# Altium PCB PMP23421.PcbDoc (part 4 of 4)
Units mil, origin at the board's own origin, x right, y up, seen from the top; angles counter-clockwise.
Board outline 2755.91 x 7559.06 mil, 8 copper layers (Top Layer, Signal Layer 1, Signal Layer 2, Signal Layer 3, Signal Layer 4, Signal Layer 5, Signal Layer 6, Bottom Layer), stack 60.4 mil thick; 211 components, 135 nets, 708 pads, 652 vias.
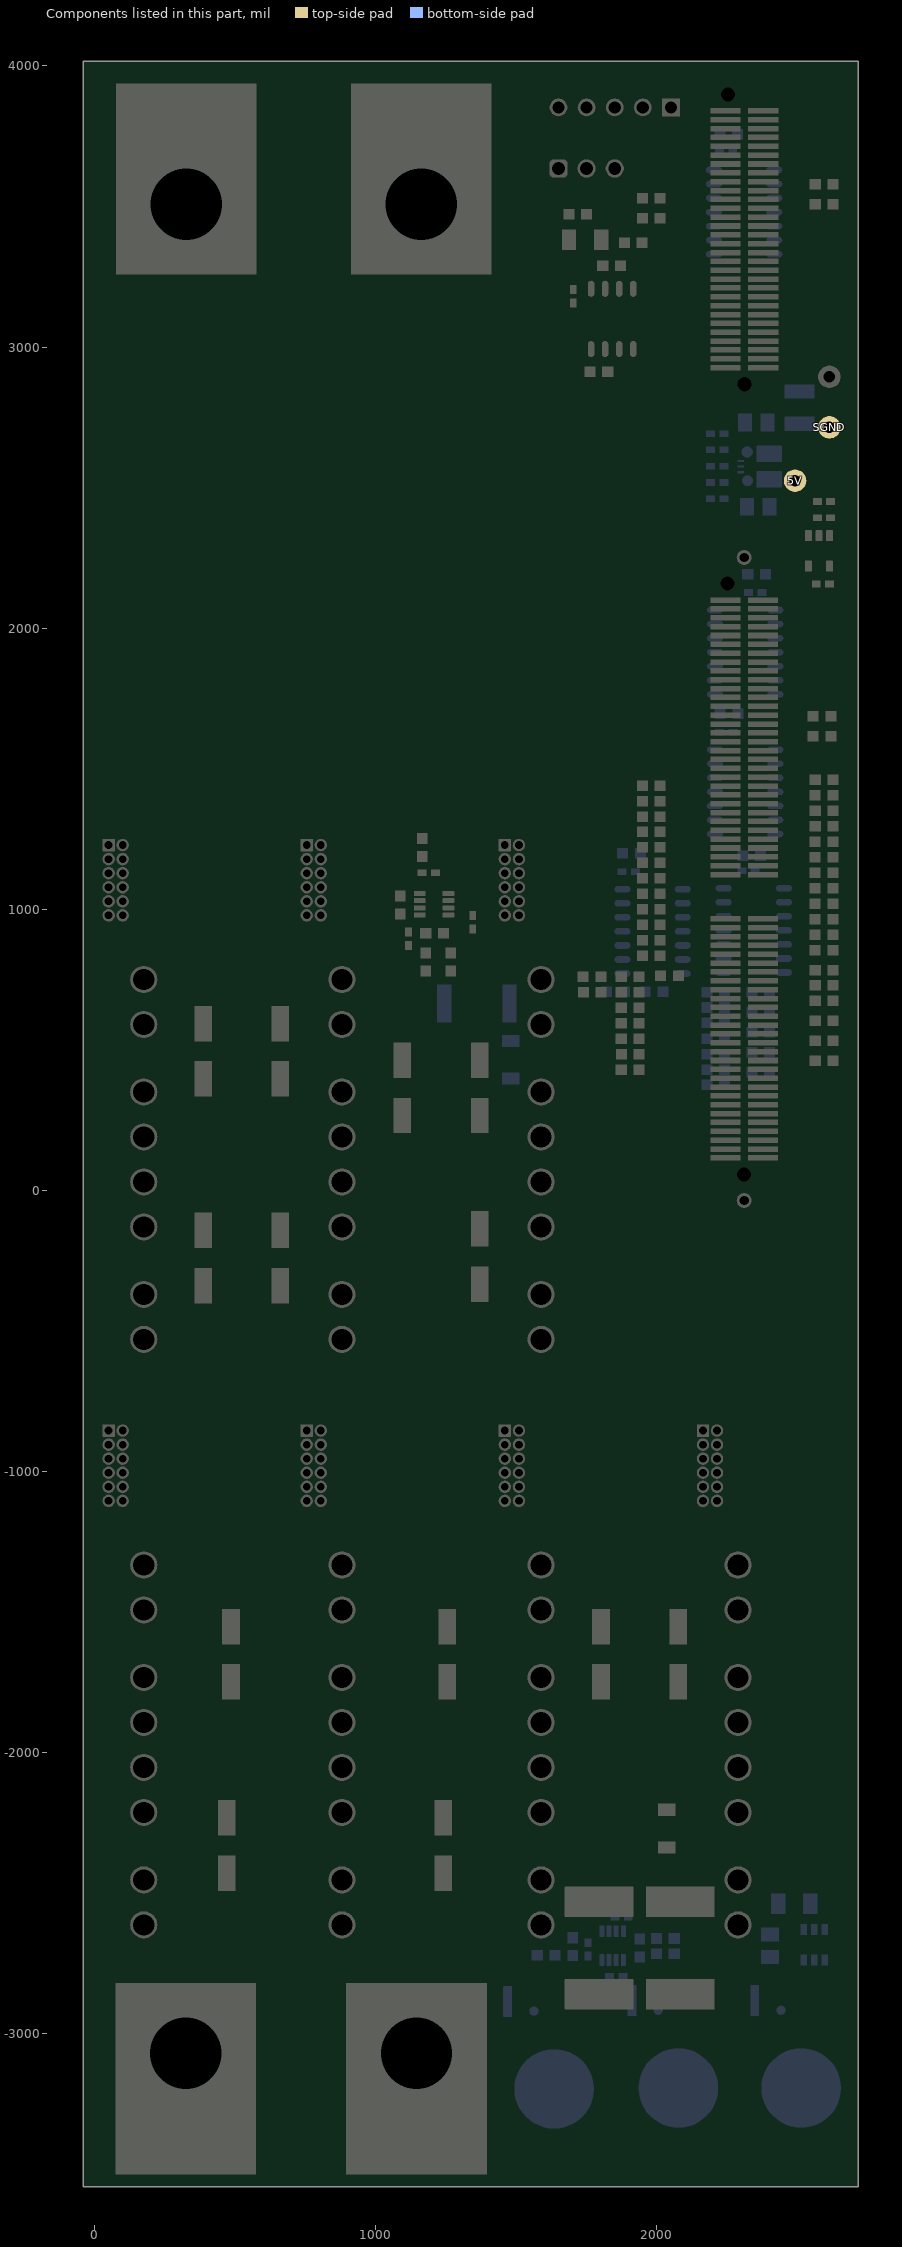
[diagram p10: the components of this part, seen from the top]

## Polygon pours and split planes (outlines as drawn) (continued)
VBAT- on Signal Layer 1 "VBAT-" (solid, remove dead copper, pour order 167): -20,-1960 2390,-1960 2390,-1183.1 2356.91,-1150 1765,-1150 1699.53,-1082.22 1699.53,1525.47 1580,1645 1580,3950 1535,3995 650,3995 605,3950 605,3255 580,3230 10,3230 -20,3200 -20,-1707.96 -18.98,-1708.98 -20,-1710
48VOUT2 on Signal Layer 1 "48Vout2" (solid, remove dead copper, pour order 149): 895.77,-2819.23 850,-2865 850,-3488.58 901.42,-3540 2660,-3540 2715,-3485 2715,-3045 2685,-3015 1465,-3015 1435,-2985 1435,-2860 1394.23,-2819.23
CS-_total_discharge_current_bus on Signal Layer 1 "CS-_total_discharge_current_bus" (solid, remove dead copper, pour order 218): 1900,-2750 1910,-2760 1910,-2785 1920,-2795 1960,-2795 1970,-2785 1970,-2760 1980,-2750 2065,-2750 2065,-2940 1520,-2940 1487.2,-2907.2 1487.2,-2782.8 1520,-2750
CS-_total_discharge_current_bus on Signal Layer 1 "CS-_total_discharge_current_bus" (solid, remove dead copper, pour order 306): 2093.91,-2750 2650.64,-2750 2700,-2799.36 2700,-2910 2670,-2940 2093.91,-2940
SGND on Signal Layer 1 "SGND" (solid, remove dead copper, pour order 332): -18.98,-1975 2390,-1975 2390,-2290.17 2340.17,-2340 1920.27,-2340 1511.68,-2748.59 741.41,-2748.59 700,-2790 700,-3490 665,-3525 14.61,-3525 -18.98,-3491.41
no net on Signal Layer 1 "VBAT-" (solid, remove dead copper, pour order 346): -20,-1960 2390,-1960 2390,-1183.1 2356.91,-1150 1765,-1150 1699.53,-1082.22 1699.53,1525.47 1580,1645 1580,3950 1535,3995 650,3995 605,3950 605,3255 580,3230 10,3230 -20,3200 -20,-1707.96 -18.98,-1708.98 -20,-1710
SGND on Signal Layer 2 "SGND" (solid, remove dead copper, pour order 296): 2450,-2325 2450,-2720 2669.61,-2720 2715.4,-2674.21 2715.4,-1125.22 2715,-1124.82 2715,3970 2685,4000 1640,4000 1588.33,3948.33 1588.55,1701.89 1710,1580.43 1710,-994.12 1850.7,-1134.82 2410,-1134.82 2450,-1174.82
VBAT- on Signal Layer 2 "VBAT-" (solid, remove dead copper, pour order 294): 765,2158.96 945,1978.96 945,1410 1030,1325 1490.71,1325 1580.71,1415 1580.71,2135 1580.71,3969.29 1554.64,3995.36 791.5,3995.36 765,3968.86
CS-_total_charge_current_battery on Signal Layer 2 "CS-_total_charge_current_battery" (solid, remove dead copper, pour order 288): -30,2225 -30,555.1 0,525.1 905.34,525.1 936.42,556.17 936.42,1970.91 748.66,2158.66 750,2160 750,4000 30,4000 -30,3940
CS-_total_charge_current_battery on Signal Layer 2 "CS-" (solid, remove dead copper, pour order 286): 20,-1180 -20,-1220 -20,-1575 20,-1615 2338.59,-1615 2378.59,-1575 2378.59,-1223.59 2335,-1180
SGND on Signal Layer 2 "SGND" (solid, remove dead copper, pour order 276): 14.61,-2715 -18.98,-2748.59 -18.98,-3491.41 14.61,-3525 665,-3525 700,-3490 700,-2750 665,-2715
48VOUT1 on Signal Layer 2 "48Vout1" (solid, remove dead copper, pour order 268): 15,-2310 -18.98,-2343.98 -18.98,-2666.02 15,-2700 1890,-2700 2395,-2700 2435,-2660 2435,-2345.79 2399.21,-2310
CS-_total_charge_current_battery on Signal Layer 2 "CS-_total_charge_current_battery" (solid, remove dead copper, pour order 264): 130,525 105,550 105,790 130,815 911.42,815 936.42,790 936.42,556.42 905,525
48VOUT1 on Signal Layer 2 "48Vout1" (solid, remove dead copper, pour order 250): 125,-265 105,-285 105,-575 125,-595 930,-595 950,-575 950,-285 930,-265
5V on Signal Layer 2 "5V" (solid, remove dead copper, pour order 139): 2443.65,2558.35 2462.77,2577.46 2518.93,2577.46 2533.44,2562.95 2533.44,2497.36 2513.72,2477.64 2467.46,2477.64 2453.68,2463.86 2453.68,2391.02 2447.77,2385.12 2374.94,2385.12 2369.03,2391.02 2369.03,2463.86 2369.03,2554.41 2372.97,2558.35
5V on Signal Layer 2 "5V" (solid, remove dead copper, pour order 178): 2372.97,2558.35 2369.03,2554.41 2369.03,2463.86 2369.03,2391.02 2374.94,2385.12 2447.77,2385.12 2453.68,2391.02 2453.68,2546.54 2441.87,2558.35
48VOUT2 on Signal Layer 2 "48Vout2" (solid, remove dead copper, pour order 153): 870,-2755 850,-2775 850,-3488.58 901.42,-3540 2660,-3540 2715,-3485 2715,-3045 2685,-3015 1465,-3015 1435,-2985 1435,-2820 1370,-2755
CS-_total_discharge_current_bus on Signal Layer 2 "CS-_total_discharge_current_bus" (solid, remove dead copper, pour order 220): 1900,-2750 1910,-2760 1910,-2785 1920,-2795 1960,-2795 1970,-2785 1970,-2760 1980,-2750 2650.64,-2750 2700,-2799.36 2700,-2910 2670,-2940 1520,-2940 1487.2,-2907.2 1487.2,-2782.8 1520,-2750
SGND on Signal Layer 2 "SGND" (solid, remove dead copper, pour order 254): 1670,-181.02 1631.02,-220 1630,-220 -5,-220 -18.98,-206.02 -18.98,110 1670,110 1670,-50
VBAT- on Signal Layer 2 "VBAT-" (solid, remove dead copper, pour order 312): -18.98,120 -18.98,496.02 0,515 924.4,515 1040.29,399.11 1645.9,399.11 1670,375.01 1670,120
SGND on Signal Layer 2 "SGND" (solid, remove dead copper, pour order 314): -18.98,-1975 2380,-1975 2380,-2258.59 2343.59,-2295 15,-2295 -18.98,-2261.02
VBAT- on Signal Layer 2 "VBAT-" (solid, remove dead copper, pour order 316): 15,-1630 2333.59,-1630 2380,-1676.41 2380,-1975 -18.98,-1975 -18.98,-1663.98
SGND on Signal Layer 3 "SGND" (solid, remove dead copper, pour order 298): 1710,1231.5 1703.5,1225 1626.94,1225 1556.94,1155 1492.92,1155 1485,1147.08 1485,936.31 1515,906.31 1710,906.31 1710,-994.12 1850.7,-1134.82 2410,-1134.82 2450,-1174.82 2450,-2720 2669.61,-2720 2715.4,-2674.21 2715.4,-1125.22 2715,-1124.82 2715,3970 2685,4000 1639.92,4000 1589.95,3950.03 1590.16,1700.27 1710,1580.43
VBAT- on Signal Layer 3 "VBAT-" (solid, remove dead copper, pour order 292): 765,2158.96 945,1978.96 945,1410 1030,1325 1490.71,1325 1580.71,1415 1580.71,2135 1580.71,3949.29 1534.64,3995.36 810.36,3995.36 765,3950
CS-_total_charge_current_battery on Signal Layer 3 "CS-_total_charge_current_battery" (solid, remove dead copper, pour order 290): -25,2225 -25,555.1 5,525.1 910.34,525.1 941.42,556.17 941.42,1970.91 753.66,2158.66 755,2160 755,4000 35,4000 -25,3940
CS-_total_charge_current_battery on Signal Layer 3 "CS-" (solid, remove dead copper, pour order 284): 20,-1180 -20,-1220 -20,-1575 20,-1615 2338.59,-1615 2378.59,-1575 2378.59,-1223.59 2335,-1180
SGND on Signal Layer 3 "SGND" (solid, remove dead copper, pour order 274): 14.61,-2715 -18.98,-2748.59 -18.98,-3491.41 14.61,-3525 665,-3525 700,-3490 700,-2750 665,-2715
48VOUT1 on Signal Layer 3 "48Vout1" (solid, remove dead copper, pour order 266): 15,-2310 -18.98,-2343.98 -18.98,-2666.02 15,-2700 1890,-2700 2395,-2700 2435,-2660 2435,-2345.79 2399.21,-2310
CS-_total_charge_current_battery on Signal Layer 3 "CS-_total_charge_current_battery" (solid, remove dead copper, pour order 262): 130,525 105,550 105,790 130,815 911.42,815 936.42,790 936.42,556.42 905,525
SGND on Signal Layer 3 "SGND" (solid, remove dead copper, pour order 258): 1670,-181.02 1631.02,-220 1630,-220 20,-220 -18.98,-181.02 -18.98,110 1670,110 1670,-50
48VOUT1 on Signal Layer 3 "48Vout1" (solid, remove dead copper, pour order 252): 125,-265 105,-285 105,-575 125,-595 930,-595 950,-575 950,-285 930,-265
5V on Signal Layer 3 "5V" (solid, remove dead copper, pour order 138): 2443.65,2558.35 2462.77,2577.46 2518.93,2577.46 2533.44,2562.95 2533.44,2497.36 2513.72,2477.64 2467.46,2477.64 2453.68,2463.86 2453.68,2391.02 2447.77,2385.12 2374.94,2385.12 2369.03,2391.02 2369.03,2463.86 2369.03,2554.41 2372.97,2558.35
5V on Signal Layer 3 "5V" (solid, remove dead copper, pour order 177): 2372.97,2558.35 2369.03,2554.41 2369.03,2463.86 2369.03,2391.02 2374.94,2385.12 2447.77,2385.12 2453.68,2391.02 2453.68,2546.54 2441.87,2558.35
48VOUT2 on Signal Layer 3 "48Vout2" (solid, remove dead copper, pour order 152): 895.77,-2819.23 850,-2865 850,-3488.58 901.42,-3540 2660,-3540 2715,-3485 2715,-3045 2685,-3015 1450,-3015 1435,-3000 1435,-2860 1394.23,-2819.23
CS-_total_discharge_current_bus on Signal Layer 3 "CS-_total_discharge_current_bus" (solid, remove dead copper, pour order 216): 1900,-2750 1910,-2760 1910,-2785 1920,-2795 1960,-2795 1970,-2785 1970,-2760 1980,-2750 2650.64,-2750 2700,-2799.36 2700,-2910 2670,-2940 1520,-2940 1487.2,-2907.2 1487.2,-2782.8 1520,-2750
SGND on Signal Layer 3 "SGND" (solid, remove dead copper, pour order 318): -18.98,-1975 2380,-1975 2380,-2258.59 2343.59,-2295 15,-2295 -18.98,-2261.02
VBAT- on Signal Layer 3 "VBAT-" (solid, remove dead copper, pour order 320): 15,-1630 2333.59,-1630 2380,-1676.41 2380,-1975 -18.98,-1975 -18.98,-1663.98
VBAT- on Signal Layer 3 "VBAT-" (solid, remove dead copper, pour order 322): -18.98,120 -18.98,496.02 0,515 924.4,515 1040.29,399.11 1645.9,399.11 1670,375.01 1670,120
VBAT- on Signal Layer 4 "VBAT-" (solid, remove dead copper, pour order 302): 1580.35,3949.65 1534.64,3995.36 810.36,3995.36 765,3950 765,2158.96 945,1978.96 945,1410 1027.2,1327.8 1482.8,1327.8 1580.71,1425.71 1580.71,2135 1580.71,3949.29
CS-_total_charge_current_battery on Signal Layer 4 "CS-_total_charge_current_battery" (solid, remove dead copper, pour order 300): -25,2225 -25,555.1 5,525.1 910.34,525.1 941.42,556.17 941.42,1970.91 753.66,2158.66 755,2160 755,4000 35,4000 -25,3940
SGND on Signal Layer 4 "SGND" (solid, remove dead copper, pour order 270): 15,-2715 -18.59,-2748.59 -18.59,-3491.41 15,-3525 665.39,-3525 700.39,-3490 700.39,-2750 665.39,-2715
CS-_total_charge_current_battery on Signal Layer 4 "CS-_total_charge_current_battery" (solid, remove dead copper, pour order 260): 130,525 105,550 105,790 130,815 911.42,815 936.42,790 936.42,556.42 905,525
5V on Signal Layer 4 "5V" (solid, remove dead copper, pour order 140): 2443.65,2558.35 2462.77,2577.46 2518.93,2577.46 2533.44,2562.95 2533.44,2497.36 2513.72,2477.64 2467.46,2477.64 2453.68,2463.86 2453.68,2391.02 2447.77,2385.12 2374.94,2385.12 2369.03,2391.02 2369.03,2463.86 2369.03,2554.41 2372.97,2558.35
48VOUT1 on Signal Layer 4 "48VOUT1" (solid, remove dead copper, pour order 185): 2426.12,-2700 2436.12,-2690 2647.96,-2690 2670,-2667.96 2670,-1235 2595,-1160 2126.54,-1160 1885,-918.46 1885,-715 1760,-590 1555,-590 1525.61,-560.61 1525.61,-311.1 1479.51,-265 15,-265 -20,-300 -20,-2675 5,-2700 465,-2700 1820,-2700 1973.26,-2700
48VOUT2 on Signal Layer 4 "48Vout2" (solid, remove dead copper, pour order 150): 880.77,-2819.23 850,-2850 850,-3488.58 901.42,-3540 2660,-3540 2715,-3485 2715,-3045 2685,-3015 1465,-3015 1435,-2985 1435,-2855 1399.23,-2819.23
CS-_total_discharge_current_bus on Signal Layer 4 "CS-_total_discharge_current_bus" (solid, remove dead copper, pour order 214): 1900,-2750 1910,-2760 1910,-2785 1920,-2795 1960,-2795 1970,-2785 1970,-2760 1980,-2750 2650.64,-2750 2700,-2799.36 2700,-2910 2670,-2940 1520,-2940 1487.2,-2907.2 1487.2,-2782.8 1520,-2750
SGND on Signal Layer 4 "SGND" (solid, remove dead copper, pour order 240): 1610,3955 1588.45,3933.45 1588.45,1413.45 1495,1320 0,1320 -20,1300 -20,885 5,860 1665,860 1710,815 1710,-525 1893.72,-708.72 1893.72,-917.23 2129.37,-1152.88 2662.12,-1152.88 2705,-1110 2705,3875 2625,3955
SGND on Signal Layer 4 "SGND" (solid, remove dead copper, pour order 326): 1670,-181.02 1631.02,-220 1630,-220 -5,-220 -18.98,-206.02 -18.98,110 1670,110 1670,-50
VBAT- on Signal Layer 4 "VBAT-" (solid, remove dead copper, pour order 328): -18.98,120 -18.98,496.02 0,515 924.4,515 1040.29,399.11 1645.9,399.11 1670,375.01 1670,120
SGND on Signal Layer 5 "SGND" (solid, remove dead copper, pour order 334): 1699.53,90 1700.27,89.26 1700.27,-190.27 2124.3,-614.3 2124.3,-1814.3 2260.99,-1950.99 2345.99,-1950.99 2390,-1995 2390,-2290.17 2340.17,-2340 1920.27,-2340 1511.68,-2748.59 891.41,-2748.59 820,-2820 820,-3495 790,-3525 14.61,-3525 -18.98,-3491.41 -18.98,90
SGND on Signal Layer 5 "SGND" (solid, remove dead copper, pour order 336): 1710,-185 1765,-240 2132.95,-607.95 2132.95,-1097.78 2175,-1139.82 2365,-1139.82 2405,-1179.82 2405,-2290 2345,-2350 1925,-2350 1825,-2450 1825,-2684.61 1870.39,-2730 2660,-2730 2700,-2690 2700,3935 2640,3995 1635,3995 1590,3950 1590,3938.81 1590.22,1650.22 1710,1530.43
48VOUT2 on Signal Layer 5 "48Vout2" (solid, remove dead copper, pour order 338): 895.77,-2819.23 850,-2865 850,-3488.58 901.42,-3540 2660,-3540 2715,-3485 2715,-3045 2685,-3015 1465,-3015 1435,-2985 1435,-2860 1394.23,-2819.23
CS-_total_discharge_current_bus on Signal Layer 5 "CS-_total_discharge_current_bus" (solid, remove dead copper, pour order 340): 1900,-2750 1910,-2760 1910,-2785 1920,-2795 1960,-2795 1970,-2785 1970,-2760 1980,-2750 2650.64,-2750 2700,-2799.36 2700,-2910 2670,-2940 1520,-2940 1487.2,-2907.2 1487.2,-2782.8 1520,-2750
CS-_total_charge_current_battery on Signal Layer 5 "CS-_total_charge_current_battery" (solid, remove dead copper, pour order 342): 750,3950 700,4000 30,4000 -30,3940 -30,2225 -30,555.1 0,525.1 905.34,525.1 936.42,556.17 936.42,1970.91 748.66,2158.66 750,2160
VBAT- on Signal Layer 5 "VBAT-" (solid, remove dead copper, pour order 344): 945,1410 945,550.91 909.09,515 0,515 -25,490 -25,100 1700.27,100 1700.27,1524.71 1580.71,1645 1580.71,2135 1580.71,3969.29 1554.64,3995.36 791.5,3995.36 765,3968.86 765,2158.96 945,1978.96
SGND on Signal Layer 6 "SGND" (solid, remove dead copper, pour order 348): 1699.53,90 1700.27,89.26 1700.27,-190.27 2124.3,-614.3 2124.3,-1814.3 2260.99,-1950.99 2345.99,-1950.99 2390,-1995 2390,-2290.17 2340.17,-2340 1920.27,-2340 1511.68,-2748.59 891.41,-2748.59 820,-2820 820,-3495 790,-3525 14.61,-3525 -18.98,-3491.41 -18.98,90
48VOUT2 on Signal Layer 6 "48Vout2" (solid, remove dead copper, pour order 350): 895.77,-2819.23 850,-2865 850,-3488.58 901.42,-3540 2660,-3540 2715,-3485 2715,-3045 2685,-3015 1465,-3015 1435,-2985 1435,-2860 1394.23,-2819.23
CS-_total_discharge_current_bus on Signal Layer 6 "CS-_total_discharge_current_bus" (solid, remove dead copper, pour order 352): 1900,-2750 1910,-2760 1910,-2785 1920,-2795 1960,-2795 1970,-2785 1970,-2760 1980,-2750 2650.64,-2750 2700,-2799.36 2700,-2910 2670,-2940 1520,-2940 1487.2,-2907.2 1487.2,-2782.8 1520,-2750
SGND on Signal Layer 6 "SGND" (solid, remove dead copper, pour order 354): 1710,-185 1765,-240 2132.95,-607.95 2132.95,-1097.78 2175,-1139.82 2365,-1139.82 2405,-1179.82 2405,-2290 2345,-2350 1925,-2350 1825,-2450 1825,-2684.61 1870.39,-2730 2660,-2730 2700,-2690 2700,3935 2640,3995 1635,3995 1590,3950 1590,3938.81 1590.22,1650.22 1710,1530.43
VBAT- on Signal Layer 6 "VBAT-" (solid, remove dead copper, pour order 356): 945,1410 945,550.91 909.09,515 0,515 -25,490 -25,100 1700.27,100 1700.27,1524.71 1580.71,1645 1580.71,2135 1580.71,3969.29 1554.64,3995.36 791.5,3995.36 765,3968.86 765,2158.96 945,1978.96
CS-_total_charge_current_battery on Signal Layer 6 "CS-_total_charge_current_battery" (solid, remove dead copper, pour order 358): 750,3951.15 700,4001.15 30,4001.15 -30,3941.15 -30,2226.15 -30,556.25 0,526.25 905.34,526.25 936.42,557.32 936.42,1972.07 748.66,2159.82 750,2161.15

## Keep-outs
Keep-Out Layer:
  text ".Layer_Name" at 60.15,-4415.31 h60

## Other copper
Top Layer:
  text ".Layer_Name" at 60.15,-4415.31 h60
Signal Layer 2:
  pour cut-out: 2245,-2593.24 2245,-2620 2275,-2620 2275,-2593.24
Signal Layer 1:
  pour cut-out: 760.72,-925.18 760.72,-1134.82 837.05,-1134.82 837.05,-925.18
  pour cut-out: 758.67,1160.37 758.67,950.73 835,950.73 835,1160.37
  pour cut-out: 53.67,1156.03 53.67,946.38 130,946.38 130,1156.03
  pour cut-out: 1463.67,1153.97 1463.67,944.32 1540,944.32 1540,1153.97
  pour cut-out: 1469.89,-930.18 1469.89,-1139.82 1546.22,-1139.82 1546.22,-930.18
  pour cut-out: 54.89,-928.7 54.89,-1138.35 131.22,-1138.35 131.22,-928.7
Signal Layer 4:
  pour cut-out: 2245,-2593.24 2245,-2620 2275,-2620 2275,-2593.24
Signal Layer 5:
  pour cut-out: 54.89,-930.18 54.89,-1139.82 131.22,-1139.82 131.22,-930.18
  pour cut-out: 760,-930.18 760,-1139.82 836.33,-1139.82 836.33,-930.18
  pour cut-out: 1464.89,-931.65 1464.89,-1141.3 1541.22,-1141.3 1541.22,-931.65
Signal Layer 6:
  pour cut-out: 54.89,-930.18 54.89,-1139.82 131.22,-1139.82 131.22,-930.18
  pour cut-out: 760,-930.18 760,-1139.82 836.33,-1139.82 836.33,-930.18
  pour cut-out: 1464.89,-931.65 1464.89,-1141.3 1541.22,-1141.3 1541.22,-931.65
Bottom Layer:
  text ".Layer_Name" at 60.15,-4415.31 h60

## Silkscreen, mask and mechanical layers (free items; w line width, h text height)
Top Overlay:
  lines w10: 1290.25,1094.39 1290.25,1290 1290.25,1315.25 1415,1440 1600,1440 1730,1570 ; 1640,1772.44 1640,1845 1640,2040 1735,2135 1764.53,2135 1805.2,2094.33 1805.2,2044.8 1955,1895 1955,1695 1890,1630 1890,1589 1866,1565 1740,1565 1725,1580 ; 1662.44,1640 1724.97,1577.46 1727.54,1577.46 ; 1750.27,361.14 1750.27,445.74 1799.53,495 1815,495 ; 1875,360 2095,360 2116.54,338.46 2116.54,282.08 2020,185.54 2020,5 1960,-55 1850.53,-55 1816.54,-21.01 1816.54,97.99 1690,224.53 1690,335 1715,360 1880,360 ; 1970,2770.47 1977.13,2777.6 2096.93,2777.6 2120,2754.53 2120,2515.55 2094.45,2490 1965,2490 1949.53,2505.47 1949.53,2750 1974.53,2775 1975,2775 ; 2120,2745 2470,2745 2580,2635 2580,2505 ; 2595,385 2605,375 2605,320
  text "PMP23421_Main_Rev B" at 29.94,260 h80 r270
  text "PMP23421_Main_RevC" at 2580,-810 h100 r270
  text ".Layer_Name" at 60.15,-4415.31 h60
Bottom Overlay:
  lines w10: 1880,-2145 2029.46,-2145 2110,-2225.54 2110,-2366.54 2031.54,-2445 1750,-2445 1695,-2390 1514.53,-2390 1490,-2365.47 1490,-2325 1525.9,-2289.1 1600.9,-2289.1 1745,-2145 1895,-2145 ; 1910,-2530 1955,-2485 1955,-2445 ; 2295.56,240.3 2295.56,325 ; 2471.4,240 2475,240 2490.03,224.97 2490.03,-44.97 2375,-160 2130,-160 2114.46,-144.46 2114.46,189.19 2165.57,240.3 2475,240.3
  text ".Layer_Name" at 60.15,-4415.31 h60
Top Paste:
  text ".Layer_Name" at 60.15,-4415.31 h60
Bottom Paste:
  text ".Layer_Name" at 60.15,-4415.31 h60
Top Solder:
  rectangle: 2375,-685 2530,-245
  rectangle: 2099.53,-705 2311.66,-240
  rectangle: 960,1460 1545,2200
  rectangle: 780,2225 1551.18,3180
  rectangle: 0,1375 730,3180
  rectangle: 2136.11,419.34 2167.61,442.96
  rectangle: 2134.14,3828.79 2165.64,3852.41
  rectangle: 2136.11,3482.33 2171.54,3505.95
  rectangle: 2145.95,1742.17 2165.64,1765.79
  rectangle: 2145.95,1773.67 2165.64,1795.32
  rectangle: 2145.95,1805.16 2167.61,1828.79
  rectangle: 2145.95,1962.64 2165.64,1984.3
  rectangle: 2143.98,828.79 2171.54,852.41
  rectangle: 2453.04,576.82 2502.25,600.44
  rectangle: 2439.26,858.31 2484.54,883.9
  rectangle: 2437.29,891.78 2484.54,915.4
  rectangle: 2437.29,923.27 2484.54,946.9
  rectangle: 2439.26,1095 2465,1135.87
  rectangle: 2439.26,1143.75 2480.6,1167.76
  rectangle: 2444.25,1269.73 2471.56,1293.35
  rectangle: 2439.26,1301.23 2481.24,1322.88
  rectangle: 2437.29,1395.71 2490.44,1417.37
  rectangle: 2437.29,1427.21 2486.5,1450.83
  rectangle: 2435.32,1771.7 2512.09,1797.29
  rectangle: 2435.32,1960.67 2502.25,1986.27
  rectangle: 2143.98,1364.22 2175.48,1387.84
  rectangle: 2143.98,1332.72 2173.51,1356.34
  rectangle: 2143.98,1301.23 2173.51,1324.85
  rectangle: 2143.98,1269.73 2175.48,1293.35
  rectangle: 2143.98,1206.54 2175.48,1230.36
  rectangle: 2143.98,1175.24 2177.45,1198.86
  rectangle: 2143.98,1143.75 2171.54,1167.37
  rectangle: 2143.98,1112.25 2177.45,1135.87
  rectangle: 2122.33,954.77 2173.51,976.42
  rectangle: 2100.68,923.27 2175.48,946.9
  rectangle: 2128.24,891.78 2175.48,913.43
  rectangle: 2128.24,860.28 2169.57,881.93
  rectangle: 2138.08,608.31 2173.51,631.93
  rectangle: 2138.08,513.82 2171.54,537.45
  rectangle: 2138.08,482.33 2173.51,503.98
  rectangle: 2138.08,452.8 2173.51,472.49
  rectangle: 2132.17,354.38 2183.35,379.97
  rectangle: 2453.04,322.88 2500.28,348.07
  rectangle: 2449.1,419.34 2478.63,442.96
  rectangle: 2456.98,480.36 2500.28,505.95
  rectangle: 2453.04,1931.15 2500.28,1952.8
  rectangle: 2455.01,1899.65 2502.25,1923.27
  rectangle: 2455.01,1868.16 2502.25,1889.81
  rectangle: 2458.94,1836.66 2502.25,1860.28
  rectangle: 2458.94,1805.16 2502.25,1828.79
  rectangle: 2453.04,1710.67 2498.31,1734.3
  rectangle: 2453.04,1679.18 2498.31,1702.8
  rectangle: 2453.04,1647.68 2499.72,1671.3
  rectangle: 2453.04,1614.22 2491.39,1639.81
  rectangle: 2453.04,1584.69 2488.47,1608.31
  rectangle: 2453.04,1553.19 2488.47,1576.82
  rectangle: 2458.94,1490.2 2494.38,1513.82
  rectangle: 2458.94,1458.71 2496.35,1482.33
  rectangle: 1439.96,-3522.92 2677.08,-2985
  rectangle: 1480,-2945 2695,-2740
  rectangle: 2130,3515 2180,3535
  rectangle: 2128.54,3450 2171.54,3475
  rectangle: 2440,3545 2500.64,3565
  rectangle: 2430,3515 2500.64,3535
  rectangle: 2445,3482.33 2496.35,3505
  rectangle: 1670,-2460 1985,-2320
  rectangle: 2085,-2465 2205,-2325
  rectangle: 260,-2695 800,-2510
  rectangle: 960.25,-2695 1509.45,-2510
  text ".Layer_Name" at 60.15,-4415.31 h60
  text ".Layer_Name" at 60.15,-4415.31 h60
Bottom Solder:
  rectangle: 2535,-305 2675,365
  rectangle: 1435,-3545 2715,-3365
  rectangle: 965,-2790 1425,-1600
  rectangle: 261.77,-2790 805,-2005
  rectangle: 900,1630 1509.45,3035
  rectangle: 40,1360 740,3035
  rectangle: 1025,-1550 1340,350
  rectangle: 335,-1550 700,800
  rectangle: 1685,-1565 2001.4,-945
  text ".Layer_Name" at 60.15,-4415.31 h60
Drill Guide:
  text ".Layer_Name" at 60.15,-4415.31 h60
M1 Board Outline:
  the board outline again, w7.01
  text ".Layer_Name" at 60.15,-4415.31 h60
M2 Board Dimensions:
  rectangle: -391.85,-3956.81 -16.85,-3831.81
  rectangle: -516.85,-3831.81 -391.85,-3706.81
  lines w7: -516.85,-3831.81 483.15,-3831.81 ; -391.85,-3956.81 -391.85,-3706.81 ; -266.85,-3956.81 -266.85,-3706.81 ; -16.85,-3956.81 -16.85,-3706.81 ; 233.15,-3956.81 233.15,-3706.81 ; -516.85,-3956.81 -516.85,-3706.81 483.15,-3706.81 483.15,-3956.81 -516.85,-3956.81
  text ".Layer_Name" at 60.15,-4415.31 h60
M3 3D STEP Top:
  text ".Layer_Name" at 60.15,-4415.31 h60
M4 3D STEP Bottom:
  text ".Layer_Name" at 60.15,-4415.31 h60
M5 Assembly Top:
  lines w10: -808.85,-4486.98 5791.15,-4486.98 ; -808.85,-4283.65 5793.15,-4283.65 ; -808.85,-4080.31 -808.85,-4690.31 3196.15,-4690.31 5793.15,-4690.31 5793.15,-4080.31 -808.35,-4080.31 -808.35,-4690.31 767.15,-4690.31 ; 1656.15,-4690.31 1656.15,-4080.31 ; 2923.15,-4283.65 2923.15,-4080.31 ; 3763.15,-4283.65 3763.15,-4080.31 ; 4385.15,-4696.81 4385.15,-4493.98
  text "COMPONENTS MARKED 'DNP' SHOULD NOT BE POPULATED." at 636.65,-3875.31 h60
  text "ASSEMBLY VARIANT:" at 636.15,-3990.81 h60
  text ".VariantName" at 1672.15,-3990.81 h60
  text "PCB VIEWED FROM TOP SIDE" at -745.35,-4212.48 h60
  text "BOARD #:" at 1731.15,-4212.48 h60
  text ".PRJ_Number" at 2276.65,-4212.48 h60
  text "REV:" at 3121.15,-4212.48 h60
  text ".PCB_Rev" at 3412.65,-4212.48 h60
  text "SVN REV:" at 3959.15,-4212.48 h60
  text ".VersionControl_RevNumber" at 4465.15,-4212.48 h60
  text "TID #:" at 1731.15,-4415.81 h60
  text ".TID" at 2276.65,-4415.81 h60
  text "PLOT NAME =" at -745.35,-4621.15 h60
  text ".plot_File_Name" at 60.15,-4621.15 h60
  text "GENERATED    :" at 1733.15,-4621.15 h60
  text ".Print_Date" at 2602.65,-4621.15 h60
  text ".Print_Time" at 3331.65,-4621.15 h60
  text "TEXAS INSTRUMENTS" at 4596.15,-4621.15 h60
M6 Assembly Bottom:
  lines w10: -809.35,-4284.15 5792.65,-4284.15 ; -807.35,-4487.48 5792.65,-4487.48 ; 598.65,-4697.31 598.65,-4494.48 ; 1220.65,-4284.15 1220.65,-4080.81 ; 2060.65,-4284.15 2060.65,-4080.81 ; 3327.65,-4690.81 3327.65,-4080.81 ; 4216.65,-4690.81 5792.15,-4690.81 5792.15,-4080.81 -809.35,-4080.81 -809.35,-4690.81 1787.65,-4690.81 5792.65,-4690.81 5792.65,-4080.81
  text "COMPONENTS MARKED 'DNP' SHOULD NOT BE POPULATED." at 5585.15,-3874.81 h60
  text ".VariantName" at 4541.15,-3990.81 h60
  text "ASSEMBLY VARIANT:" at 5580.15,-3990.81 h60
  text ".VersionControl_RevNumber" at 518.65,-4212.98 h60
  text "SVN REV:" at 1024.65,-4212.98 h60
  text ".PCB_Rev" at 1571.15,-4212.98 h60
  text "REV:" at 1862.65,-4212.98 h60
  text ".PRJ_Number" at 2707.15,-4212.98 h60
  text "BOARD #:" at 3252.65,-4212.98 h60
  text "PCB VIEWED FROM BOTTOM SIDE" at 5729.15,-4212.98 h60
  text ".TID" at 2707.15,-4416.31 h60
  text "TID #:" at 3252.65,-4416.31 h60
  text "TEXAS INSTRUMENTS" at 387.65,-4621.65 h60
  text ".Print_Time" at 1652.15,-4621.65 h60
  text ".Print_Date" at 2381.15,-4621.65 h60
  text "GENERATED    :" at 3250.65,-4621.65 h60
  text ".plot_File_Name" at 4923.65,-4621.65 h60
  text "PLOT NAME =" at 5729.15,-4621.65 h60
M9 Title Sheet:
  drawing of 57 lines, arcs and shapes, not listed
  text "2" at 2523,4479.88 h70
  text "1" at 222.99,4479.69 h70
  text "3" at 5207.99,4479.69 h70
  text "4" at 7714.66,4479.69 h70
  text "5" at 10213.65,4479.69 h70
  text "6" at 12718.65,4479.69 h70
  text "A" at -933.35,3336.69 h70
  text "A" at 13866.65,3336.69 h70
  text "B" at -933.35,956.69 h70
  text "B" at 13866.65,956.69 h70
  text "C" at -933.35,-1418.31 h70
  text "C" at 13866.65,-1418.31 h70
  text "PROJECT TITLE:" at 10826.65,-3279.31 h45
  text ".PRJ_Title" at 10876.65,-3412.64 h70
  text "DESIGNED FOR:" at 10826.65,-3580.31 h45
  text ".PRJ_Customer" at 10876.65,-3720.31 h70
  text "D" at -933.35,-3788.31 h70
  text "D" at 13866.65,-3788.31 h70
  text "FILE NAME:" at 10826.65,-3880.31 h45
  text ".PCB_File_Name_No_Path" at 10876.65,-4000.31 h70
  text "Texas Instruments (TI) and/or its licensors do not warrant the accuracy or completeness of this specification" at 5857.15,-4162.15 h45
  text "ENGINEER:" at 10826.65,-4170.31 h45
  text "LAYOUT BY:" at 12331.65,-4170.31 h45
  text "or any information contained therein. TI and/or its licensors do not warrant that this design will meet" at 5812.16,-4274.82 h45
  text ".PRJ_Engineer" at 10876.65,-4325.31 h70
  text ".PCB_Layout" at 12382.15,-4325.31 h70
  text "the specifications, will be suitable for your application or fit for any particular purpose, or will operate in" at 5812.16,-4387.48 h45
  text ".Layer_Name" at 60.15,-4415.31 h60
  text "ALTIUM DESIGNER VERSION:" at 12331.65,-4480.31 h45
  text "an implementation. TI and/or its licensors do not warrant that the design is production worthy. You should" at 5812.16,-4500.15 h45
  text "completely validate and test your design implementation to confirm the system functionality for your application." at 5857.15,-4612.81 h45
  text ".print_Scale" at 10876.65,-4613.64 h70
  text ".Application_BuildNumber" at 12382.15,-4613.64 h70
  text "1" at 222.99,-4820.31 h70
  text "2" at 2718.65,-4820.31 h70
  text "3" at 5207.99,-4820.31 h70
  text "4" at 7714.66,-4820.31 h70
  text "5" at 10213.65,-4820.31 h70
  text "6" at 12718.65,-4820.31 h70
M10 Fab Notes:
  drawing of 189 lines, arcs and shapes, not listed
  text "DESIGN INFORMATION" at 11865.17,2799.36 h60
  text "MIN. TRACK WIDTH:" at 11220.61,2667.23 h60
  text "8" at 12316.85,2667.24 h60
  text "MIL" at 12471.61,2667.23 h60
  text "MIN. CLEARANCE:" at 11220.61,2543.11 h60
  text "0.2" at 12256.85,2543.11 h60
  text "mm" at 12471.61,2543.11 h60
  text "MIN. VIA PAD SIZE:" at 11220.61,2418.98 h60
  text "24" at 12286.86,2418.99 h60
  text "MIL" at 12471.61,2418.98 h60
  text "0.05mm (2MIL)" at 11915.61,2289.08 h60
  text "MINIMUM ANNULAR RING" at 10891.38,2280.86 h60
  text "EXTERNAL" at 12623.61,2280.86 h60
  text "PER" at 11091.38,2170.73 h60
  text "IPC-D-275 CLASS 2 LEVEL C" at 11311.38,2170.73 h60
  text "MIL, HOLES" at 12799.61,2070.25 h60
  text "+/-" at 12407.15,2061.67 h60
  text "+/-" at 13261.15,2061.67 h60
  text "REGISTRATION TOLERANCES:" at 10891.38,2060.6 h60
  text "METAL" at 12091.15,2060.6 h60
  text "5" at 12667.35,2060.61 h60
  text "3" at 13500.35,2060.61 h60
  text "MIL" at 13616.61,2060.6 h60
  text "HOLE SIZE TOLERANCE (UNLESS OTHERWISE SPECIFIED):" at 10891.38,1962.29 h60
  text "+/-" at 13261.15,1959.42 h60
  text "3" at 13500.35,1958.36 h60
  text "MIL" at 13616.61,1958.35 h60
  text "MATERIAL:" at 10816.61,1820.71 h60
  text "FR-4 High Tg" at 11803.05,1692.18 h60
  text "X" at 11658.61,1684.19 h60
  text "FR-408" at 11237.61,1679.67 h60
  text "OTHER" at 12725.61,1679.67 h60
  text "62 MIL (1.6mm) +/-10%" at 11557.71,1536.64 h60
  text "X" at 11437.61,1534.19 h60
  text "THICKNESS:" at 10891.38,1528.42 h60
  text "OTHER" at 12842.61,1528.42 h60
  text "TOLERANCE:" at 10891.38,1390.11 h60
  text "X" at 11739.61,1390.11 h60
  text "ANSI IPC-6012 TYPE 3 CLASS 2" at 11917.63,1390.11 h60
  text "OTHER +/-" at 11917.61,1245.92 h60
  text "BOW & TWIST:" at 10891.38,1100.73 h60
  text "X" at 11739.61,1100.73 h60
  text "ANSI IPC-6012 TYPE 3 CLASS 2" at 11917.63,1100.73 h60
  text "OTHER +/-" at 11917.61,954.03 h60
  text "DRILLING:" at 10816.61,823.42 h60
  text "NC_DRILL FILES" at 12577.61,718.23 h60
  text "REFERENCE:" at 10891.38,714.29 h60
  text "X" at 11548.61,714.19 h60
  text "AS SHOWN" at 11726.61,714.29 h60
  text "X" at 12449.61,714.29 h60
  text "OTHER" at 12875.61,572.04 h60
  text "PTH COPPER THICKNESS:" at 10891.06,568.51 h60
  text "X" at 12030.29,568.51 h60
  text "20-30 um" at 12158.29,568.51 h60
  text "BOARD FINISH:" at 10816.61,420.91 h60
  text "SILKSCREEN:" at 10971.83,310.79 h60
  text "X" at 11929.61,310.79 h60
  text "TOP" at 12046.61,310.79 h60
  text "X" at 12439.61,310.79 h60
  text "BOTTOM" at 12557.61,310.79 h60
  text "SILKSCREEN COLOR:" at 10971.83,155.6 h60
  text "X" at 11928.61,155.6 h60
  text "WHITE" at 12046.61,155.6 h60
  text "OTHER" at 12557.61,155.6 h60
  text "X" at 12059.61,12.15 h60
  text "GREEN" at 12177.61,12.15 h60
  text "OTHER" at 12795.61,12.15 h60
  text "SOLDER RESIST COLOR:" at 10971.83,5.28 h60
  text "X" at 12059.61,-142.1 h60
  text "MATTE" at 12177.61,-142.1 h60
  text "SEMI-GLOSS" at 12795.15,-142.74 h60
  text "IMMERSION GOLD (ENIG)" at 11877.61,-314.88 h60
  text "ENEPIG" at 13215.15,-322.1 h60
  text "SURFACE FINISH:" at 10816.61,-323.1 h60
  text "X" at 11699.61,-323.1 h60
  text "IMM. TIN/SILVER OR EQUIV" at 11146.15,-460.41 h60
  text "OTHER" at 12577.61,-464.35 h60
  text "ARRAY/PANEL:" at 10816.61,-619.73 h60
  text "CUT AND TRIM PER M1 BOARD OUTLINE" at 11877.61,-627.95 h60
  text "N.C. ROUTE" at 11877.61,-763.92 h60
  text "X" at 12565.61,-763.92 h60
  text "V. SCORE" at 12743.61,-763.92 h60
  text "CERTIFICATION:" at 10816.61,-893.04 h60
  text "MATERIALS AND WORKMANSHIP FOR ALL PCBS" at 11541.61,-893.04 h60
  text "TO MEET OR EXCEED THE REQUIREMENTS OF:" at 11541.61,-987.1 h60
  text "X" at 11179.12,-1115.73 h60
  text "ANSI IPC-A-600F CLASS ->" at 11307.11,-1115.73 h60
  text "X" at 12955.12,-1115.73 h60
  text "2" at 13065.11,-1115.73 h60
  text "1" at 12750.11,-1117.23 h60
  text "3" at 13419.11,-1117.23 h60
  text "X" at 11991.12,-1263.42 h60
  text "RoHS" at 12119.11,-1263.42 h60
  text "OTHER" at 12763.51,-1263.42 h60
  text "PER ORDER" at 13160.57,-1263.42 h60
  text "ALL BOARDS MUST MEET OR EXCEED UL94-V0 REQUIREMENTS." at 10844.15,-1417.25 h60
  text "PCB MUST BEAR THE UL94V-0 UL REGISTERED MATERIAL ID NUMBER" at 10844.15,-1533.31 h60
  text "ADDITIONAL REQUIREMENTS:" at 10816.61,-1702.73 h60
  text "MICROSECTION:" at 10891.38,-1809.86 h60
  text "YES" at 11797.11,-1809.86 h60
  text "REQUIRED" at 12658.61,-1954.19 h60
  text "BARE BOARD ELEC. TEST:" at 10891.38,-1957.05 h60
  text "NONE" at 12197.11,-1957.05 h60
  text "X" at 12540.61,-1957.05 h60
  text "PER ORDER" at 13250.61,-1957.05 h60
  text "XX MIL VIAS REQUIRE NON-CONDUCTIVE FILL AND PLANARIZE" at 11059.53,-2162 h59
  text "XX MIL VIAS REQUIRE CONDUCTIVE FILL AND PLANARIZE" at 11067.53,-2265.97 h60
  text "OUTER XX MIL TRACES REQUIRE 50 OHM SINGLE-ENDED IMPEDANCE" at 11066.54,-2429.36 h58
  text "LAYER 2 & 3 (INNER LAYERS) XX MIL WIDE, XX MIL SPACE / TRACES REQUIRE 100 OHM DIFFERENTIAL IMPEDANCE" at 11058.54,-2665.07 h60
  text ".Layer_Name" at 60.15,-4415.31 h60
M11 Gerber Information:
  lines w10: -808.85,-4486.98 5791.15,-4486.98 ; -808.85,-4283.65 5793.15,-4283.65 ; -808.85,-4080.31 -808.85,-4690.31 3196.15,-4690.31 5793.15,-4690.31 5793.15,-4080.31 -808.35,-4080.31 -808.35,-4690.31 767.15,-4690.31 ; 1656.15,-4690.31 1656.15,-4080.31 ; 2923.15,-4283.65 2923.15,-4080.31 ; 3763.15,-4283.65 3763.15,-4080.31 ; 4385.15,-4696.81 4385.15,-4493.98
  text "ALL ARTWORK VIEWED FROM TOP SIDE" at -745.35,-4212.48 h60
  text "BOARD #:" at 1731.15,-4212.48 h60
  text ".PRJ_Number" at 2276.65,-4212.48 h60
  text "REV:" at 3121.15,-4212.48 h60
  text ".PCB_Rev" at 3412.65,-4212.48 h60
  text "SVN REV:" at 3959.15,-4212.48 h60
  text ".VersionControl_RevNumber" at 4465.15,-4212.48 h60
  text "LAYER NAME =" at -745.35,-4415.31 h60
  text "TID #:" at 1731.15,-4415.81 h60
  text ".TID" at 2276.65,-4415.81 h60
  text "PLOT NAME =" at -745.35,-4621.15 h60
  text ".plot_File_Name" at 60.15,-4621.15 h60
  text "GENERATED    :" at 1733.15,-4621.15 h60
  text ".Print_Date" at 2602.65,-4621.15 h60
  text ".Print_Time" at 3331.65,-4621.15 h60
  text "TEXAS INSTRUMENTS" at 4596.15,-4621.15 h60
M12 Stackup:
  drawing of 503 lines, arcs and shapes, not listed
  text "Layer" at 5547.2,3495.35 h60
  text "Name" at 5957.11,3495.35 h60
  text "Material" at 6896.85,3495.35 h60
  text "Thickness" at 7756.62,3495.35 h60
  text "Constant" at 8406.46,3495.35 h60
  text "Board Layer Stack" at 8976.32,3495.35 h60
  text "1" at 5547.2,3375.35 h60
  text "Top Overlay" at 5957.11,3375.35 h60
  text "2" at 5547.2,3255.35 h60
  text "Top Solder" at 5957.11,3255.35 h60
  text "Solder Resist" at 6896.85,3255.35 h60
  text "0.39mil" at 7756.62,3255.35 h60
  text "3.5" at 8406.46,3255.35 h60
  text "3" at 5547.2,3135.35 h60
  text "Top Layer" at 5957.11,3135.35 h60
  text "Copper" at 6896.85,3135.35 h60
  text "2.80mil" at 7756.62,3135.35 h60
  text "4" at 5547.2,3015.35 h60
  text "Dielectric1" at 5957.11,3015.35 h60
  text "FR-4" at 6896.85,3015.35 h60
  text "5.00mil" at 7756.62,3015.35 h60
  text "4.2" at 8406.46,3015.35 h60
  text "5" at 5547.2,2895.35 h60
  text "Signal Layer 1" at 5957.11,2895.35 h60
  text "Copper" at 6896.85,2895.35 h60
  text "2.80mil" at 7756.62,2895.35 h60
  text "6" at 5547.2,2775.35 h60
  text "Dielectric 2" at 5957.11,2775.35 h60
  text "FR-4" at 6896.85,2775.35 h60
  text "6.00mil" at 7756.62,2775.35 h60
  text "4.2" at 8406.46,2775.35 h60
  text "7" at 5547.2,2655.35 h60
  text "Signal Layer 2" at 5957.11,2655.35 h60
  text "Copper" at 6896.85,2655.35 h60
  text "2.80mil" at 7756.62,2655.35 h60
  text "8" at 5547.2,2535.35 h60
  text "Dielectric 3" at 5957.11,2535.35 h60
  text "5.00mil" at 7756.62,2535.35 h60
  text "4.2" at 8406.46,2535.35 h60
  text "9" at 5547.2,2415.35 h60
  text "Signal Layer 3" at 5957.11,2415.35 h60
  text "Copper" at 6896.85,2415.35 h60
  text "2.80mil" at 7756.62,2415.35 h60
  text "10" at 5547.2,2295.35 h60
  text "Dielectric 4" at 5957.11,2295.35 h60
  text "6.00mil" at 7756.62,2295.35 h60
  text "4.2" at 8406.46,2295.35 h60
  text "11" at 5547.2,2175.35 h60
  text "Signal Layer 4" at 5957.11,2175.35 h60
  text "Copper" at 6896.85,2175.35 h60
  text "2.80mil" at 7756.62,2175.35 h60
  text "12" at 5547.2,2055.35 h60
  text "Dielectric 6" at 5957.11,2055.35 h60
  text "5.00mil" at 7756.62,2055.35 h60
  text "4.2" at 8406.46,2055.35 h60
  text "13" at 5547.2,1935.35 h60
  text "Signal Layer 5" at 5957.11,1935.35 h60
  text "Copper" at 6896.85,1935.35 h60
  text "2.80mil" at 7756.62,1935.35 h60
  text "14" at 5547.2,1815.35 h60
  text "Dielectric 7" at 5957.11,1815.35 h60
  text "6.00mil" at 7756.62,1815.35 h60
  text "4.2" at 8406.46,1815.35 h60
  text "15" at 5547.2,1695.35 h60
  text "Signal Layer 6" at 5957.11,1695.35 h60
  text "Copper" at 6896.85,1695.35 h60
  text "2.80mil" at 7756.62,1695.35 h60
  text "16" at 5547.2,1575.35 h60
  text "Dielectric 5" at 5957.11,1575.35 h60
  text "5.00mil" at 7756.62,1575.35 h60
  text "4.2" at 8406.46,1575.35 h60
  text "17" at 5547.2,1455.35 h60
  text "Bottom Layer" at 5957.11,1455.35 h60
  text "Copper" at 6896.85,1455.35 h60
  text "2.80mil" at 7756.62,1455.35 h60
  text "18" at 5547.2,1335.35 h60
  text "Bottom Solder" at 5957.11,1335.35 h60
  text "Solder Resist" at 6896.85,1335.35 h60
  text "0.39mil" at 7756.62,1335.35 h60
  text "3.5" at 8406.46,1335.35 h60
  text "19" at 5547.2,1215.35 h60
  text "Bottom Overlay" at 5957.11,1215.35 h60
  text ".Layer_Name" at 60.15,-4415.31 h60
M13 Component Bodies Top:
  text ".Layer_Name" at 60.15,-4415.31 h60
M14 Component Bodies Bottom:
  text ".Layer_Name" at 60.15,-4415.31 h60
M15 Courtyards Top:
  text ".Layer_Name" at 60.15,-4415.31 h60
M16 Courtyards Bottom:
  text ".Layer_Name" at 60.15,-4415.31 h60
Drill Drawing:
  circle w10: c5479.15,915.59 r27.63
  circle w10: c5479.15,666.95 r16.58
  circle w10: c5479.15,666.95 r27.63
  lines w10: 5451.52,-479.56 5479.15,-465.75 5506.77,-479.56 5492.96,-451.93 5506.77,-424.31 5479.15,-438.12 5451.52,-424.31 5465.33,-451.93 5451.52,-479.56 ; 5451.52,-341.43 5465.33,-341.43 5479.15,-355.24 5492.96,-341.43 5506.77,-341.43 5492.96,-327.61 5506.77,-313.8 5492.96,-313.8 5479.15,-299.99 5465.33,-313.8 5451.52,-313.8 5465.33,-327.61 5451.52,-341.43 ; 5451.52,-203.29 5479.15,-230.92 5506.77,-203.29 5479.15,-175.67 5451.52,-203.29 ; 5451.52,-106.6 5506.77,-106.6 5506.77,-51.35 5451.52,-51.35 5451.52,-106.6 ; 5451.52,17.72 5451.52,31.53 5465.33,45.35 5451.52,59.16 5451.52,72.97 5465.33,72.97 5479.15,59.16 5492.96,72.97 5506.77,72.97 5506.77,59.16 5492.96,45.35 5506.77,31.53 5506.77,17.72 5492.96,17.72 5479.15,31.53 5465.33,17.72 5451.52,17.72 ; 5451.52,155.85 5465.33,155.85 5479.15,142.04 5492.96,155.85 5506.77,155.85 5492.96,169.67 5506.77,183.48 5492.96,183.48 5479.15,197.29 5465.33,183.48 5451.52,183.48 5465.33,169.67 5451.52,155.85 ; 5451.52,321.61 5506.77,321.61 5479.15,266.36 5451.52,321.61 ; 5451.52,404.49 5465.33,404.49 5465.33,390.68 5492.96,390.68 5492.96,404.49 5506.77,404.49 5506.77,432.12 5492.96,432.12 5492.96,445.93 5465.33,445.93 5465.33,432.12 5451.52,432.12 5451.52,404.49 ; 5451.52,570.25 5506.77,570.25 5479.15,515 5451.52,570.25 ; 5451.52,763.64 5506.77,763.64 5506.77,818.89 5451.52,818.89 5451.52,763.64 ; 5462.57,-95.55 5495.72,-95.55 5495.72,-62.4 5462.57,-62.4 5462.57,-95.55 ; 5462.57,161.38 5470.86,161.38 5479.15,153.09 5487.44,161.38 5495.72,161.38 5487.44,169.67 5495.72,177.95 5487.44,177.95 5479.15,186.24 5470.86,177.95 5462.57,177.95 5470.86,169.67 5462.57,161.38 ; 5462.57,310.56 5495.72,310.56 5479.15,277.41 5462.57,310.56
  lines w12: 5401.43,-516.86 8558.63,-516.86 ; 5401.43,974.98 8558.63,974.98 ; 5739.29,-641.18 5739.29,1099.3 ; 6040.77,-641.18 6040.77,1099.3 ; 6633.56,-641.18 6633.56,1099.3 ; 6892.7,-641.18 6892.7,1099.3 ; 7267.86,-641.18 7267.86,1099.3 ; 7992.19,-641.18 7992.19,1099.3 ; 5401.43,-641.18 8558.63,-641.18 8558.63,1099.3 5401.43,1099.3 5401.43,-641.18
  text "Symbol" at 5476.02,1012.28 h72
  text "Count" at 5776.59,1012.28 h72
  text "Hole Size" at 6078.06,1012.28 h72
  text "Plated" at 6670.86,1012.28 h72
  text "Hole Type" at 6930,1012.28 h72
  text "Drill Layer Pair" at 7305.16,1012.28 h72
  text "Hole Tolerance" at 8029.49,1012.28 h72
  text "12" at 5776.59,887.96 h60
  text "7.87mil (0.200mm)" at 6078.06,887.96 h60
  text "PTH" at 6670.86,887.96 h60
  text "Round" at 6930,887.96 h60
  text "Top Layer - Bottom Layer" at 7305.16,887.96 h60
  text "401" at 5776.59,763.64 h60
  text "10.00mil (0.254mm)" at 6078.06,763.64 h60
  text "PTH" at 6670.86,763.64 h60
  text "Round" at 6930,763.64 h60
  text "Top Layer - Bottom Layer" at 7305.16,763.64 h60
  text "232" at 5776.59,639.32 h60
  text "16.00mil (0.406mm)" at 6078.06,639.32 h60
  text "PTH" at 6670.86,639.32 h60
  text "Round" at 6930,639.32 h60
  text "Top Layer - Bottom Layer" at 7305.16,639.32 h60
  text "7" at 5776.59,515 h60
  text "25.00mil (0.635mm)" at 6078.06,515 h60
  text "PTH" at 6670.86,515 h60
  text "Round" at 6930,515 h60
  text "Top Layer - Bottom Layer" at 7305.16,515 h60
  text "84" at 5776.59,390.68 h60
  text "27.56mil (0.700mm)" at 6078.06,390.68 h60
  text "PTH" at 6670.86,390.68 h60
  text "Round" at 6930,390.68 h60
  text "Top Layer - Bottom Layer" at 7305.16,390.68 h60
  text "2" at 5776.59,266.36 h60
  text "33.07mil (0.840mm)" at 6078.06,266.36 h60
  text "PTH" at 6670.86,266.36 h60
  text "Round" at 6930,266.36 h60
  text "Top Layer - Bottom Layer" at 7305.16,266.36 h60
  text "3" at 5776.59,142.04 h60
  text "40.00mil (1.016mm)" at 6078.06,142.04 h60
  text "PTH" at 6670.86,142.04 h60
  text "Round" at 6930,142.04 h60
  text "Top Layer - Bottom Layer" at 7305.16,142.04 h60
  text "5" at 5776.59,17.72 h60
  text "43.31mil (1.100mm)" at 6078.06,17.72 h60
  text "PTH" at 6670.86,17.72 h60
  text "Round" at 6930,17.72 h60
  text "Top Layer - Bottom Layer" at 7305.16,17.72 h60
  text "3" at 5776.59,-106.6 h60
  text "45.28mil (1.150mm)" at 6078.06,-106.6 h60
  text "PTH" at 6670.86,-106.6 h60
  text "Round" at 6930,-106.6 h60
  text "Top Layer - Bottom Layer" at 7305.16,-106.6 h60
  text "4" at 5776.59,-230.92 h60
  text "50.00mil (1.270mm)" at 6078.06,-230.92 h60
  text "NPTH" at 6670.86,-230.92 h60
  text "Round" at 6930,-230.92 h60
  text "Top Layer - Bottom Layer" at 7305.16,-230.92 h60
  text "56" at 5776.59,-355.24 h60
  text "75.00mil (1.905mm)" at 6078.06,-355.24 h60
  text "PTH" at 6670.86,-355.24 h60
  text "Round" at 6930,-355.24 h60
  text "Top Layer - Bottom Layer" at 7305.16,-355.24 h60
  text "4" at 5776.59,-479.56 h60
  text "254.00mil (6.452mm)" at 6078.06,-479.56 h60
  text "PTH" at 6670.86,-479.56 h60
  text "Round" at 6930,-479.56 h60
  text "Top Layer - Bottom Layer" at 7305.16,-479.56 h60
  text "813 Total" at 5776.59,-603.88 h60
  text ".Layer_Name" at 60.15,-4415.31 h60
M17 Embedded Cavity:
  text ".Layer_Name" at 60.15,-4415.31 h60
M18 Embedded Assembly:
  text ".Layer_Name" at 60.15,-4415.31 h60
M19 Embedded Keepout:
  text ".Layer_Name" at 60.15,-4415.31 h60

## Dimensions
-516.85,-3956.81 to 483.15,-3956.81 on M2 Board Dimensions
-39.37,-3543.31 to -39.37,4015.75 on M2 Board Dimensions
-39.37,-3543.31 to 2716.54,-3543.31 on M2 Board Dimensions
